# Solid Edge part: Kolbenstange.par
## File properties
Username: bmolnar
Dokumentum tartalom típus: 0
Author: bmolnar
Last saved by: bmolnar
Revision: 93
Sűrűség: 0,000 kg/m^3
Pontosság: 0,990
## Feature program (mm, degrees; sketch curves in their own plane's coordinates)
base feature "unnamed BaseFeature 1"
sketch for "unnamed Protrusion 1" plane through (33.5, 0, 0) normal (1, 0, 0) x-axis (0, 0, 1)
  circle centre (0, 0) radius 40
extrude "unnamed Protrusion 1" add finite 19.5 along +normal
sketch for "Kihúzás_2" plane through (33.5, 0, 0) normal (1, 0, 0) x-axis (0, 0, 1)
  circle centre (0, 0) radius 40
extrude "Kihúzás_2" add finite 4.5 along -normal
sketch for "Furat_1" plane through (-120, 0, 0) normal (-1, 0, 0) x-axis (0, 0, -1)
  hole centre (0, 0) bore radius 5.053
hole "Furat_1" nominal diameter 12 finite  ThreadDepth = 20 mm
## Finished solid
Body 1: solid body, 15 faces, 21 edges, 8 vertices.
  Faces by surface: plane 8, cylinder 4, cone 2, torus 1
  Edges by curve: circle 11, line 6, ellipse 2, intersection 2
Bounding box of the edges (mm; curved faces can reach further): 173.000 x 80.000 x 80.000, from (-120, -40, -40) to (53, 40, 40).
Cylindrical faces by radius (mm): R5.053 x2, R10 x1, R40 x1
Conical faces (half-angle, radius in mm at the cone's reference point): 45 deg R5.553 x1, 59 deg R2.5265 x1
Toroidal faces (ring radius, tube radius in mm): R8.2 r1.8 x1
Planar faces by outward normal: +x 1, +z 1, -x 3, -z 1, oblique 2
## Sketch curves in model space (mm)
circle centre (33.5, 0, 0) radius 40
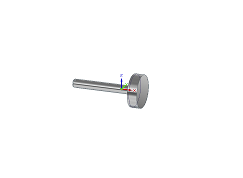
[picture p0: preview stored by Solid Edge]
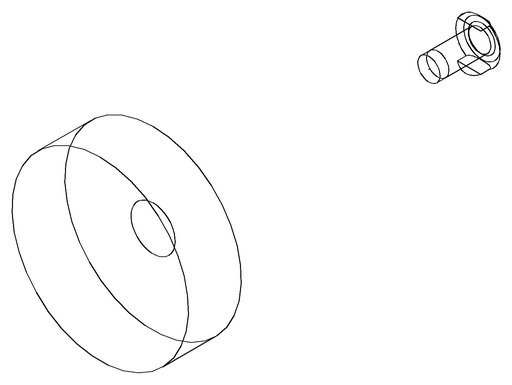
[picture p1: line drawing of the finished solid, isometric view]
